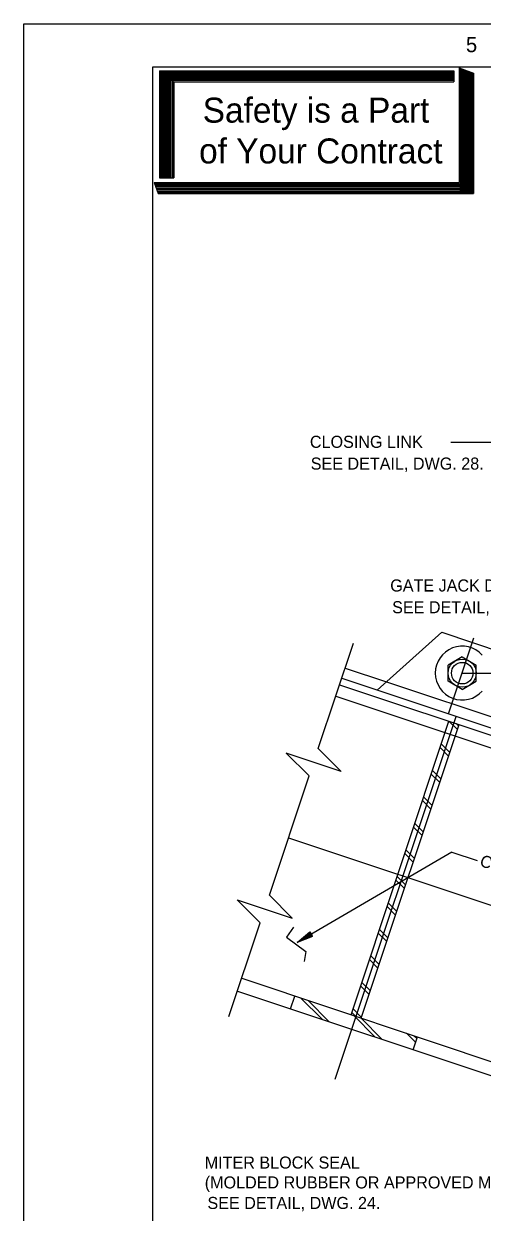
# Model space of a CAD drawing. Extents: x 0.1 to 13.5, y 0.1 to 9.5.
# Drawn here: x 0.125 to 1.9, y 4.859 to 9.458 of the extents above; entities that cross this region are included whole.
import ezdxf

# ---------------------------------------------------------------- set-up
doc = ezdxf.new("R2010")
doc.units = 0
for name, color, linetype in [('Level 1', 7, 'Continuous'), ('Level 13', 7, 'Continuous'), ('Level 25', 7, 'Continuous'), ('Level 3', 7, 'Continuous'), ('Level 44', 7, 'Continuous'), ('Level 50', 7, 'Continuous')]:
    doc.layers.add(name, color=color, linetype=linetype)

msp = doc.modelspace()

# ---------------------------------------------------------------- linework, layer by layer
at = {"layer": 'Level 1'}
for p, q in [((0.6508, 9.2759), (1.7898, 9.2759)), ((0.6508, 9.2759), (0.6508, 8.8622)), ((0.6508, 9.2706), (1.7898, 9.2706)), ((0.6508, 9.2656), (1.7898, 9.2656)), ((0.6508, 9.2602), (1.7898, 9.2602)), ((0.6508, 9.2549), (1.7898, 9.2549)), ((0.6508, 9.2499), (1.7898, 9.2499)), ((0.6561, 9.2759), (0.6561, 8.8622)), ((0.6611, 9.2759), (0.6611, 8.8622)), ((0.6664, 9.2759), (0.6664, 8.8622)), ((0.6714, 9.2759), (0.6714, 8.8622)), ((0.6768, 9.2759), (0.6768, 8.8622)), ((0.6821, 9.2759), (0.6821, 8.8622)), ((0.6871, 9.2759), (0.6871, 8.8622)), ((0.6924, 9.2759), (0.6924, 8.8622)), ((0.6978, 9.2759), (0.6978, 8.8622)), ((0.7028, 9.2759), (0.7028, 8.8622)), ((1.7898, 9.2759), (1.7898, 9.2342)), ((1.8108, 9.2882), (1.8108, 8.8436)), ((1.8108, 9.2882), (1.8664, 9.2676)), ((1.8144, 9.2869), (1.8144, 8.8019)), ((1.8194, 9.2849), (1.8194, 8.8019)), ((1.8248, 9.2829), (1.8248, 8.8019)), ((1.8301, 9.2809), (1.8301, 8.8019)), ((1.8351, 9.2792), (1.8351, 8.8019)), ((1.8404, 9.2772), (1.8404, 8.8019)), ((1.8454, 9.2752), (1.8454, 8.8019)), ((1.8508, 9.2732), (1.8508, 8.8019)), ((1.8561, 9.2716), (1.8561, 8.8019)), ((1.8611, 9.2676), (1.8611, 8.8019)), ((1.8664, 9.2676), (1.8664, 8.8019)), ((0.6508, 9.2446), (1.7898, 9.2446)), ((0.6508, 9.2396), (1.7898, 9.2396)), ((0.7064, 9.2342), (1.7898, 9.2342)), ((0.7064, 9.2342), (0.7064, 8.8622)), ((0.6298, 8.8436), (1.8108, 8.8436)), ((0.6298, 8.8436), (0.6451, 8.8019)), ((0.6318, 8.8382), (1.8144, 8.8382)), ((0.6334, 8.8332), (1.8144, 8.8332)), ((0.6508, 8.8622), (0.7064, 8.8622)), ((0.6354, 8.8279), (1.8144, 8.8279)), ((0.6374, 8.8226), (1.8144, 8.8226)), ((0.6394, 8.8176), (1.8144, 8.8176)), ((0.6414, 8.8122), (1.8144, 8.8122)), ((0.6431, 8.8072), (1.8144, 8.8072)), ((0.6451, 8.8019), (1.8664, 8.8019))]:
    msp.add_line(p, q, dxfattribs=at)
for points in [[(0.125, 9.4583), (13.4583, 9.4583), (13.4583, 0.125), (0.125, 0.125)], [(0.625, 9.2917), (13.2917, 9.2917), (13.2917, 0.2917), (0.625, 0.2917)]]:
    msp.add_lwpolyline(points, close=True, dxfattribs=at)
at = {"layer": 'Level 13'}
for p, q in [((1.8227, 7.008), (1.7681, 6.9765)), ((1.8227, 7.008), (1.8772, 6.9765)), ((1.7681, 6.9138), (1.7681, 6.9765)), ((1.8772, 6.9138), (1.8772, 6.9765)), ((1.8227, 6.8823), (1.7681, 6.9138)), ((1.8227, 6.8823), (1.8772, 6.9138))]:
    msp.add_line(p, q, dxfattribs=at)
for points in [[(1.2655, 6.6534), (1.3546, 6.5648), (1.1414, 6.6359), (1.2301, 6.547)], [(1.0407, 5.979), (0.9517, 6.0675), (1.1649, 5.9965), (1.0762, 6.0853)]]:
    msp.add_lwpolyline(points, dxfattribs=at)
msp.add_circle((1.8228, 6.9451), 0.0544, dxfattribs=at)
at = {"layer": 'Level 25'}
for p, q in [((1.7438, 7.1033), (1.4934, 6.8793)), ((1.7438, 7.1033), (1.9809, 7.0242)), ((1.2655, 6.6534), (1.4015, 7.0614)), ((1.7701, 6.787), (1.8683, 7.0815)), ((1.3693, 6.9646), (1.5292, 6.9113)), ((1.3478, 6.9003), (2.6555, 6.4644)), ((1.3561, 6.9251), (2.6347, 6.4989)), ((1.5292, 6.9113), (2.0374, 6.7419)), ((1.8228, 6.9451), (4.4466, 6.9451)), ((1.333, 6.8559), (2.5722, 6.4428)), ((1.3313, 5.3741), (1.7991, 6.7774)), ((1.3923, 5.6228), (1.7711, 6.7593)), ((1.4318, 5.6096), (1.8106, 6.7461)), ((1.0762, 6.0853), (1.2301, 6.547)), ((1.1502, 6.3074), (2.4579, 5.8715)), ((1.7827, 6.2524), (1.1841, 5.9029)), ((1.7827, 6.2524), (1.8803, 6.2199)), ((0.9196, 5.6157), (1.0407, 5.979)), ((1.1693, 5.9622), (1.1427, 5.9237)), ((1.1427, 5.9237), (1.2167, 5.8674)), ((1.2167, 5.8674), (1.2108, 5.8289)), ((0.969, 5.7639), (2.5722, 5.2295)), ((0.9526, 5.7145), (2.5722, 5.1746)), ((1.1584, 5.6458), (1.1749, 5.6953)), ((1.6328, 5.4877), (1.6492, 5.5371))]:
    msp.add_line(p, q, dxfattribs=at)
msp.add_circle((1.8228, 6.9451), 0.0417, dxfattribs=at)
msp.add_arc((1.8228, 6.9451), 0.1042, 41.8103, 318.1897, dxfattribs=at)
at = {"layer": 'Level 3'}
msp.add_lwpolyline([(1.7783, 7.8386), (2.1006, 7.8386), (2.8149, 7.0196)], dxfattribs=at)
at = {"layer": 'Level 44'}
for p, q in [((1.8041, 6.7265), (1.7716, 6.7591)), ((1.8088, 6.7407), (1.7998, 6.7497)), ((1.7747, 6.6381), (1.7417, 6.6711)), ((1.7699, 6.624), (1.737, 6.6569)), ((1.7358, 6.5215), (1.7028, 6.5544)), ((1.7405, 6.5356), (1.7075, 6.5686)), ((1.7016, 6.4189), (1.6686, 6.4519)), ((1.7063, 6.4331), (1.6734, 6.466)), ((1.6674, 6.3164), (1.6345, 6.3494)), ((1.6721, 6.3306), (1.6392, 6.3635)), ((1.6379, 6.228), (1.605, 6.261)), ((1.6332, 6.2139), (1.6003, 6.2468)), ((1.5991, 6.1113), (1.5661, 6.1443)), ((1.6038, 6.1255), (1.5708, 6.1584)), ((1.5649, 6.0088), (1.5319, 6.0418)), ((1.5696, 6.023), (1.5367, 6.0559)), ((1.5307, 5.9063), (1.4978, 5.9392)), ((1.5354, 5.9204), (1.5025, 5.9534)), ((1.5012, 5.8179), (1.4683, 5.8508)), ((1.4965, 5.8038), (1.4636, 5.8367)), ((1.4624, 5.7012), (1.4294, 5.7342)), ((1.4671, 5.7154), (1.4341, 5.7483)), ((1.2799, 5.6054), (1.1975, 5.6877)), ((1.3081, 5.5959), (1.2258, 5.6783)), ((1.41, 5.6169), (1.3952, 5.6316)), ((1.4329, 5.6128), (1.3999, 5.6458)), ((1.4849, 5.537), (1.4026, 5.6194)), ((1.5132, 5.5276), (1.4309, 5.6099)), ((1.6423, 5.5163), (1.6076, 5.551)), ((1.647, 5.5305), (1.6359, 5.5416))]:
    msp.add_line(p, q, dxfattribs=at)
at = {"layer": 'Level 50'}
for p, q in [((1.1841, 5.9029), (1.1841, 5.9029)), ((1.1991, 5.9117), (1.1991, 5.9117))]:
    msp.add_line(p, q, dxfattribs=at)
msp.add_lwpolyline([(1.2432, 5.9254), (1.1841, 5.9029), (1.2328, 5.9433), (1.2417, 5.928), (1.1991, 5.9117), (1.2321, 5.9391), (1.2378, 5.9293), (1.2135, 5.9201), (1.2315, 5.9349), (1.2339, 5.9308), (1.2285, 5.9288)], dxfattribs=at)

# ---------------------------------------------------------------- texts
at = {"layer": 'Level 1'}
for s, height, p in [('5', 0.0584, (1.8373, 9.3483)), ('Safety is a Part', 0.096792, (0.8179, 9.0756)), ('of Your Contract', 0.096792, (0.8039, 8.9177)), ('CLOSING LINK', 0.046698, (1.2331, 7.817)), ('SEE DETAIL, DWG. 28.', 0.046698, (1.2362, 7.7328)), ('GATE JACK DETAIL', 0.046698, (1.5441, 7.261)), ('SEE DETAIL, DWG. 24.', 0.046698, (1.5514, 7.1768)), ('MITER BLOCK SEAL', 0.046698, (0.8258, 5.0275)), ('(MOLDED RUBBER OR APPROVED MATERIAL)', 0.046698, (0.8258, 4.9505)), ('SEE DETAIL, DWG. 24.', 0.046698, (0.8363, 4.8711))]:
    msp.add_text(s, height=height, dxfattribs=at).set_placement(p)
msp.add_text('C15X33.9', height=0.0467, rotation=339.4353, dxfattribs=at).set_placement((1.8868, 6.2008))

doc.saveas('drawing.dxf')
